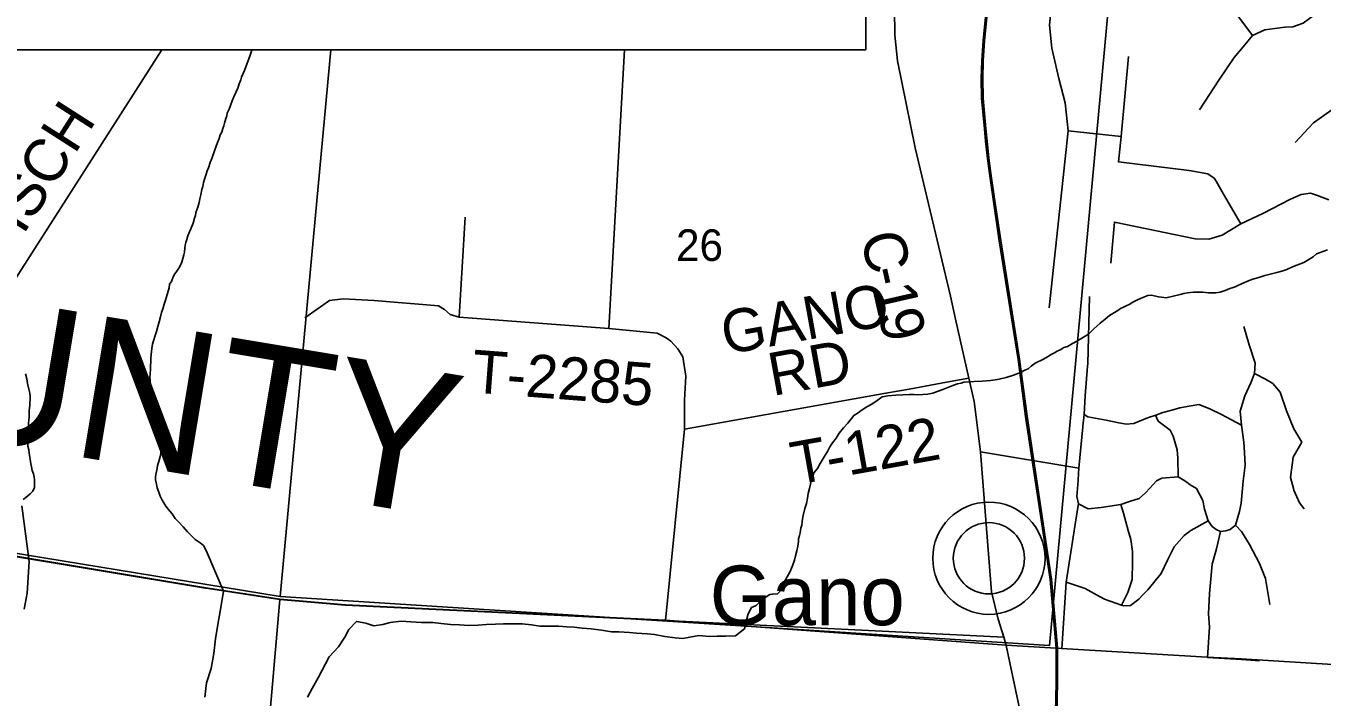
# Model space of a CAD drawing. Extents: x 0 to 34, y 0 to 22.
# Drawn here: x 6.065 to 7.782, y 14.962 to 15.851 of the extents above; entities that cross this region are included whole.
import ezdxf

# ---------------------------------------------------------------- set-up
doc = ezdxf.new("R2010")
doc.units = 0
for name, color, linetype in [('GM_X_County_Road', 7, 'Continuous'), ('GM_X_County_Road_Text', 7, 'Continuous'), ('GM_X_County_Text', 7, 'Continuous'), ('GM_X_Minor_River', 7, 'Continuous'), ('GM_X_Rail_Line', 7, 'Continuous'), ('GM_X_Section', 7, 'Continuous'), ('GM_X_Section_Text', 7, 'Continuous'), ('GM_X_Township_Road', 7, 'Continuous'), ('GM_X_Township_Road_Text', 7, 'Continuous'), ('GM_X_Unincorporated', 7, 'Continuous'), ('GM_X_Unincorporated_Location', 7, 'Continuous'), ('GM_X_Unincorporated_Text', 7, 'Continuous'), ('SH_Cut_Line', 7, 'Continuous'), ('SH_Text', 7, 'Continuous')]:
    doc.layers.add(name, color=color, linetype=linetype)

msp = doc.modelspace()

# ---------------------------------------------------------------- linework, layer by layer
at = {"layer": 'GM_X_County_Road'}
for p, q in [((7.3141, 15.3844), (7.2966, 15.4626)), ((7.3298, 15.2866), (7.3229, 15.34)), ((5.976, 15.1604), (6.3025, 15.106)), ((6.9121, 15.0631), (7.3604, 15.0411))]:
    msp.add_line(p, q, dxfattribs=at)
for points in [[(7.2966, 15.4626), (7.2898, 15.4929), (7.2433, 15.6897), (7.2199, 15.8051), (7.2161, 15.8392), (7.2144, 15.9802), (7.2122, 16.0676), (7.2136, 16.1357), (7.2136, 16.2323), (7.2152, 16.2683), (7.2204, 16.2879), (7.2343, 16.3297), (7.2592, 16.3916), (7.2625, 16.4)], [(7.3229, 15.34), (7.3211, 15.3533), (7.3141, 15.3844)], [(7.3638, 15.0301), (7.3604, 15.0411), (7.3532, 15.0648), (7.3441, 15.1013), (7.3408, 15.1457), (7.3298, 15.2866)], [(6.3025, 15.106), (6.3035, 15.1059), (6.4013, 15.0912)], [(6.3406, 14.4159), (6.3408, 14.4188), (6.3507, 14.5264), (6.3678, 14.7139), (6.3846, 14.9026), (6.4013, 15.0912)], [(6.4013, 15.0912), (6.4883, 15.0834), (6.9121, 15.0631)], [(7.332, 14.1), (7.3371, 14.1566), (7.3386, 14.1728), (7.364, 14.4409), (7.3713, 14.5158), (7.3754, 14.5663), (7.3924, 14.7336), (7.3975, 14.7638), (7.4076, 14.8037), (7.4083, 14.8085), (7.4087, 14.8124), (7.4085, 14.817), (7.4067, 14.8277), (7.3638, 15.0301)]]:
    msp.add_lwpolyline(points, dxfattribs=at)
at = {"layer": 'GM_X_Minor_River'}
for points in [[(6.305, 15.6592), (6.3066, 15.6633), (6.309, 15.6701), (6.311, 15.6754), (6.3146, 15.6856), (6.3166, 15.692), (6.3186, 15.6969), (6.3206, 15.7022), (6.3222, 15.7068), (6.3241, 15.7105), (6.3254, 15.7154), (6.327, 15.7188), (6.3278, 15.7226), (6.3294, 15.7287), (6.331, 15.7321), (6.3315, 15.7355), (6.3342, 15.7411), (6.3358, 15.7456), (6.3382, 15.7521), (6.3402, 15.7573), (6.3454, 15.769), (6.3474, 15.7747), (6.3494, 15.78), (6.3502, 15.7834), (6.3545, 15.792), (6.3574, 15.8007), (6.3601, 15.8075), (6.3617, 15.8124), (6.3637, 15.8177), (6.3645, 15.8198)], [(6.3267, 15.1021), (6.3035, 15.156), (6.2998, 15.1625), (6.2957, 15.166), (6.289, 15.1707), (6.2853, 15.1742), (6.279, 15.1808), (6.2731, 15.1874), (6.2668, 15.194), (6.2624, 15.1983), (6.2583, 15.2045), (6.2532, 15.211), (6.2499, 15.2149), (6.2473, 15.2191), (6.2451, 15.2226), (6.2426, 15.228), (6.2408, 15.2333), (6.2386, 15.2391), (6.2376, 15.2441), (6.2366, 15.2498), (6.2363, 15.2532), (6.2367, 15.2566), (6.2384, 15.2646), (6.2392, 15.2688), (6.2408, 15.274), (6.2425, 15.2805), (6.2433, 15.2846), (6.2434, 15.2896), (6.2439, 15.296), (6.2441, 15.3048), (6.2434, 15.309), (6.2431, 15.3132), (6.24, 15.3243), (6.24, 15.3277), (6.2378, 15.3312), (6.2364, 15.3346), (6.2353, 15.3381), (6.2343, 15.3434), (6.2332, 15.3472), (6.2326, 15.3533), (6.2316, 15.3602), (6.2306, 15.3682), (6.2297, 15.3751), (6.2294, 15.3819), (6.2291, 15.3857), (6.2292, 15.3903), (6.2297, 15.3964), (6.23, 15.4108), (6.2305, 15.4158), (6.2309, 15.4196), (6.2314, 15.4237), (6.2326, 15.4294), (6.2359, 15.4408), (6.2379, 15.4464), (6.2395, 15.4528), (6.2412, 15.4589), (6.2428, 15.4657), (6.2445, 15.4714), (6.2461, 15.4763), (6.2477, 15.4823), (6.2497, 15.488), (6.2509, 15.4922), (6.2546, 15.5043), (6.255, 15.5088), (6.2574, 15.5126), (6.2598, 15.5186), (6.2621, 15.5228), (6.2648, 15.5261), (6.268, 15.5314), (6.2711, 15.5382), (6.274, 15.548), (6.2748, 15.5514), (6.2753, 15.5571), (6.2757, 15.5605), (6.2766, 15.5643), (6.2778, 15.5681), (6.2794, 15.573), (6.2814, 15.5783), (6.283, 15.5824), (6.2862, 15.59), (6.2882, 15.5964), (6.2894, 15.6002), (6.2899, 15.604), (6.2926, 15.6111), (6.2943, 15.6172), (6.2951, 15.6221), (6.2964, 15.6274), (6.2977, 15.6346), (6.2989, 15.6384), (6.3001, 15.6437), (6.3017, 15.6494), (6.3034, 15.6547), (6.305, 15.6592)], [(7.5007, 15.4674), (7.5073, 15.4713), (7.5115, 15.4743), (7.5154, 15.4768), (7.5193, 15.4786), (7.5227, 15.4804), (7.5266, 15.4822), (7.5316, 15.485), (7.537, 15.4879), (7.5428, 15.4904), (7.5513, 15.4939), (7.5558, 15.4946), (7.566, 15.492), (7.5759, 15.4909), (7.5851, 15.4929), (7.5942, 15.4953), (7.5992, 15.4967), (7.6042, 15.4977), (7.6118, 15.4986), (7.6244, 15.4982), (7.6316, 15.4976), (7.6354, 15.4975), (7.6414, 15.4977), (7.6472, 15.4986), (7.6537, 15.5007), (7.6599, 15.5032), (7.6633, 15.5042), (7.6671, 15.5056), (7.6706, 15.5074), (7.6745, 15.5088), (7.6795, 15.5113), (7.6856, 15.5138), (7.6918, 15.5159), (7.6983, 15.518), (7.7063, 15.5204), (7.7224, 15.5245), (7.7289, 15.5262), (7.7355, 15.5286), (7.7432, 15.5322), (7.7582, 15.5378), (7.7706, 15.5454), (7.7748, 15.5491), (7.7894, 15.5543)], [(7.0172, 15.0524), (7.0179, 15.0617), (7.0199, 15.0654), (7.0216, 15.0722), (7.0264, 15.0804), (7.0326, 15.0833), (7.0392, 15.0903), (7.0443, 15.0939), (7.0505, 15.0975), (7.0539, 15.0982), (7.0607, 15.0984), (7.0667, 15.1054), (7.0676, 15.1134), (7.0716, 15.1182), (7.0772, 15.1275), (7.0805, 15.1358), (7.083, 15.1433), (7.0847, 15.1489), (7.0864, 15.1554), (7.0877, 15.1618), (7.0886, 15.1678), (7.0887, 15.1713), (7.0896, 15.1758), (7.0905, 15.1792), (7.0918, 15.1856), (7.0927, 15.1894), (7.0932, 15.1939), (7.0937, 15.1981), (7.0946, 15.2022), (7.0968, 15.2117), (7.0989, 15.2185), (7.1006, 15.2253), (7.1015, 15.2317), (7.1029, 15.2381), (7.1042, 15.2438), (7.1054, 15.2487), (7.1075, 15.2543), (7.1088, 15.2588), (7.1135, 15.2648), (7.1171, 15.2711), (7.1227, 15.2801), (7.1267, 15.2872), (7.1299, 15.2935), (7.1335, 15.2988), (7.1383, 15.3051), (7.1426, 15.3114), (7.1482, 15.3185), (7.1537, 15.3248), (7.1619, 15.3348), (7.1677, 15.3384), (7.1716, 15.3417), (7.179, 15.3464), (7.1848, 15.3497), (7.191, 15.3533), (7.1995, 15.3598), (7.2068, 15.3608), (7.2175, 15.362), (7.2266, 15.3624), (7.2357, 15.3629), (7.2418, 15.3627), (7.2467, 15.3622), (7.2532, 15.3628), (7.2601, 15.3633), (7.2666, 15.3646), (7.2735, 15.3671), (7.2796, 15.3696), (7.2862, 15.372), (7.2931, 15.3749), (7.2992, 15.377), (7.3042, 15.3779), (7.3077, 15.379), (7.3141, 15.3795), (7.3214, 15.3801), (7.332, 15.3805), (7.3431, 15.3813), (7.3492, 15.3823), (7.3545, 15.3832), (7.3637, 15.3852), (7.3733, 15.3884), (7.3829, 15.3919), (7.3883, 15.3948), (7.393, 15.3969), (7.3969, 15.4002), (7.4023, 15.4042), (7.4131, 15.4096), (7.4185, 15.4128), (7.4235, 15.4157), (7.4278, 15.4179), (7.4313, 15.4201), (7.4363, 15.4226), (7.4402, 15.4251), (7.4448, 15.4265), (7.4517, 15.4305), (7.4575, 15.4333), (7.4726, 15.4427), (7.48, 15.4497), (7.4882, 15.4571), (7.4948, 15.4626), (7.5007, 15.4674)], [(6.061, 15.2238), (6.0667, 15.2282), (6.0702, 15.2312), (6.0737, 15.2345), (6.0761, 15.2394), (6.0761, 15.2436), (6.0759, 15.2497), (6.0756, 15.2531), (6.0745, 15.2577), (6.0731, 15.2619), (6.0721, 15.2669), (6.0714, 15.2707), (6.0707, 15.2741), (6.0694, 15.2822), (6.069, 15.2856), (6.0684, 15.2894), (6.0673, 15.2944), (6.0674, 15.2989), (6.0672, 15.3046), (6.0674, 15.3176), (6.0679, 15.3218), (6.068, 15.3252), (6.0684, 15.3286), (6.0689, 15.3331), (6.069, 15.3415), (6.0699, 15.348), (6.07, 15.3518), (6.0701, 15.3556), (6.0705, 15.3597), (6.0699, 15.3647), (6.0685, 15.37), (6.0667, 15.3773), (6.0657, 15.3834), (6.064, 15.3903)], [(6.0691, 15.1414), (6.0593, 15.2154)], [(6.0625, 15.0783), (6.0663, 15.0996), (6.0691, 15.1414)], [(6.3017, 14.9614), (6.304, 14.9804), (6.31, 14.9998), (6.3138, 15.0195), (6.3161, 15.0389), (6.3192, 15.0579), (6.3226, 15.0776), (6.3267, 15.1021)], [(6.438, 14.9617), (6.444, 14.9733), (6.4523, 14.9879), (6.4666, 15.015), (6.479, 15.0284), (6.4873, 15.0411), (6.4924, 15.0513), (6.5029, 15.062), (6.515, 15.0599), (6.5256, 15.0562), (6.5377, 15.0578), (6.5473, 15.0607), (6.5618, 15.0623), (6.5747, 15.0616), (6.5887, 15.0605), (6.6039, 15.0606), (6.6149, 15.0592), (6.6274, 15.0578), (6.6391, 15.0575), (6.6517, 15.0568), (6.6638, 15.0569), (6.6752, 15.0578), (6.687, 15.0583), (6.6977, 15.0588), (6.7102, 15.0589), (6.7223, 15.0587), (6.7345, 15.0573), (6.7455, 15.0559), (6.7576, 15.0556), (6.7705, 15.0557), (6.7815, 15.0547), (6.791, 15.0545), (6.802, 15.0531), (6.8137, 15.0521), (6.8274, 15.0503), (6.8406, 15.0484)], [(6.8406, 15.0484), (6.8505, 15.0482), (6.8645, 15.0472), (6.874, 15.0466), (6.888, 15.0455), (6.8975, 15.0445), (6.9115, 15.0419), (6.9251, 15.0401), (6.935, 15.0395), (6.9445, 15.0412), (6.9563, 15.0432), (6.9704, 15.0421), (6.9806, 15.0423), (6.9917, 15.0424), (7.005, 15.0429), (7.0172, 15.0524)]]:
    msp.add_lwpolyline(points, dxfattribs=at)
at = {"layer": 'GM_X_Rail_Line'}
for points in [[(7.4298, 15.0266), (7.4218, 15.1177), (7.4157, 15.159), (7.3894, 15.3336), (7.3796, 15.4091), (7.3546, 15.5664), (7.3458, 15.6248), (7.3415, 15.6557), (7.3388, 15.6757), (7.3365, 15.6984), (7.3349, 15.7147), (7.3311, 15.7555), (7.3307, 15.7814), (7.3315, 15.8052), (7.333, 15.8316), (7.3366, 15.8672)], [(7.4317, 15.0268), (7.4237, 15.1179), (7.4176, 15.1593), (7.3913, 15.3339), (7.3815, 15.4094), (7.3565, 15.5667), (7.3477, 15.6251), (7.3434, 15.6559), (7.3407, 15.676), (7.3384, 15.6986), (7.3368, 15.7149), (7.333, 15.7556), (7.3326, 15.7814), (7.3334, 15.8052), (7.3349, 15.8314), (7.3385, 15.8669)], [(7.372, 14.1), (7.3761, 14.1592), (7.3883, 14.3378), (7.395, 14.4359), (7.4002, 14.513), (7.4086, 14.6353), (7.426, 14.89), (7.4283, 14.9302), (7.4294, 14.9555), (7.43, 14.986), (7.4298, 15.0266)], [(7.374, 14.1), (7.3781, 14.159), (7.3902, 14.3377), (7.3969, 14.4358), (7.4021, 14.5129), (7.4105, 14.6352), (7.428, 14.8899), (7.4303, 14.9301), (7.4313, 14.9554), (7.4319, 14.986), (7.4317, 15.0268)]]:
    msp.add_lwpolyline(points, dxfattribs=at)
at = {"layer": 'GM_X_Section'}
for points in [[(7.1778, 16.0724), (7.5157, 16.0549), (7.4213, 15.0301), (6.4015, 15.0952), (6.4689, 15.8198)], [(6.4689, 15.8198), (6.4015, 15.0952), (5.3915, 15.2602), (5.4384, 15.8198)]]:
    msp.add_lwpolyline(points, dxfattribs=at)
at = {"layer": 'GM_X_Township_Road'}
for p, q in [((6.0493, 15.5136), (6.2449, 15.8198)), ((6.837, 15.4503), (6.8578, 15.8198)), ((7.446, 15.7123), (7.5163, 15.7047)), ((6.639, 15.4654), (6.6467, 15.5978)), ((7.2351, 15.37), (7.2845, 15.379)), ((7.2845, 15.379), (7.3141, 15.3844)), ((7.6754, 15.322), (7.6737, 15.3406)), ((7.3298, 15.2866), (7.4601, 15.2652))]:
    msp.add_line(p, q, dxfattribs=at)
for points in [[(5.9659, 15.1626), (6.3032, 15.1064), (6.401, 15.0917), (6.488, 15.0839), (6.9119, 15.0636), (7.3636, 15.0306), (7.437, 15.0262), (7.6301, 15.0148), (7.6752, 15.0122), (8.168, 14.9819), (8.3833, 14.9688), (8.525, 14.938), (8.5293, 14.9371), (8.9, 14.8595), (8.9, 19.9667)], [(7.4205, 15.4776), (7.446, 15.7123), (7.442, 15.7492), (7.4336, 15.7815), (7.4242, 15.8219), (7.421, 15.8523), (7.426, 15.9018), (7.4351, 15.9323), (7.4445, 15.9558), (7.4532, 15.991), (7.468, 16.01), (7.4817, 16.0175), (7.4939, 16.0184), (7.509, 16.0182), (7.5282, 16.0121), (7.5444, 15.9926), (7.5555, 15.98), (7.5707, 15.9575), (7.5893, 15.934), (7.6138, 15.9146), (7.6236, 15.9053), (7.629, 15.9012), (7.6629, 15.8752), (7.6902, 15.8387)], [(7.6198, 15.74), (7.6457, 15.7795), (7.6657, 15.8096), (7.68, 15.8261), (7.6902, 15.8387), (7.7063, 15.8461), (7.7329, 15.8496), (7.7435, 15.8499), (7.7571, 15.8548), (7.774, 15.8674), (7.789, 15.8864), (7.8111, 15.9337), (7.8174, 15.9509), (7.8339, 15.9821), (7.8468, 15.9922), (7.8598, 15.9975), (7.9443, 15.9957)], [(7.6747, 15.5891), (7.6519, 15.6282), (7.6421, 15.6454), (7.6393, 15.6497), (7.631, 15.6551), (7.6064, 15.6596), (7.5127, 15.671), (7.5163, 15.7047), (7.5258, 15.8108)], [(7.8252, 15.7559), (7.7954, 15.74), (7.7709, 15.723), (7.7467, 15.6967)], [(7.5023, 15.5369), (7.5072, 15.5912), (7.614, 15.5691), (7.6323, 15.5688), (7.6501, 15.574), (7.6747, 15.5891), (7.7037, 15.6028), (7.7405, 15.6217), (7.7545, 15.628), (7.7669, 15.6294), (7.7761, 15.6266), (7.7911, 15.6207)], [(6.9121, 15.0631), (6.9376, 15.3167), (6.9375, 15.3553), (6.9393, 15.3869), (6.9351, 15.4128), (6.9284, 15.4233), (6.9193, 15.4335), (6.913, 15.438), (6.9014, 15.444), (6.837, 15.4503), (6.639, 15.4654), (6.6268, 15.4689), (6.6194, 15.4755), (6.6113, 15.4801), (6.5263, 15.4874), (6.485, 15.4895), (6.4668, 15.4874), (6.4345, 15.4643)], [(7.4714, 15.4005), (7.4717, 15.4036), (7.4743, 15.4926)], [(7.6737, 15.3406), (7.6799, 15.361), (7.6879, 15.3782), (7.6928, 15.3907), (7.6935, 15.4045), (7.6856, 15.4287), (7.6788, 15.4529)], [(7.4652, 15.3198), (7.4653, 15.3209), (7.4672, 15.3362), (7.4684, 15.3608), (7.4714, 15.4005)], [(7.7443, 15.238), (7.7407, 15.2527), (7.7442, 15.2798), (7.7554, 15.2997), (7.745, 15.3172), (7.7351, 15.341), (7.7267, 15.3659), (7.7172, 15.3772), (7.7075, 15.3833), (7.6928, 15.3907)], [(6.9376, 15.3167), (7.2044, 15.3644), (7.2351, 15.37)], [(7.4672, 15.3362), (7.472, 15.3332), (7.4961, 15.3289), (7.5108, 15.3258), (7.5229, 15.3235), (7.5328, 15.3243), (7.5511, 15.332), (7.562, 15.3353), (7.5714, 15.3391), (7.5832, 15.3418)], [(7.5832, 15.3418), (7.594, 15.3451), (7.6061, 15.3471), (7.6192, 15.3497), (7.6338, 15.3437), (7.649, 15.3362), (7.6754, 15.322)], [(7.6029, 15.2464), (7.5984, 15.2495), (7.5917, 15.2535), (7.591, 15.2783), (7.5902, 15.2896), (7.5848, 15.3077), (7.581, 15.3157), (7.5652, 15.3276), (7.563, 15.3322), (7.562, 15.3353)], [(7.6675, 15.1897), (7.6727, 15.2076), (7.6751, 15.2189), (7.6776, 15.248), (7.6803, 15.2693), (7.6797, 15.2858), (7.6786, 15.2997), (7.6754, 15.322)], [(7.4597, 15.2584), (7.4601, 15.2652), (7.4652, 15.3198)], [(7.4579, 15.2077), (7.4595, 15.2178), (7.4572, 15.2277), (7.4591, 15.2488), (7.4597, 15.2584)], [(7.4595, 15.2178), (7.4723, 15.2114), (7.4896, 15.2132), (7.5158, 15.217), (7.5273, 15.2208), (7.54, 15.2248), (7.5482, 15.2324), (7.5539, 15.2385), (7.5584, 15.2437), (7.5628, 15.2485), (7.57, 15.2517), (7.5917, 15.2535)], [(7.6675, 15.1897), (7.6605, 15.1838), (7.655, 15.1819), (7.6478, 15.1813), (7.6421, 15.184), (7.6368, 15.1878), (7.6314, 15.1955), (7.6264, 15.2106), (7.6241, 15.2221), (7.6157, 15.2381), (7.6075, 15.2432), (7.6029, 15.2464)], [(7.7584, 15.2114), (7.7522, 15.2193), (7.7447, 15.236), (7.7443, 15.238)], [(7.4373, 15.0256), (7.4432, 15.1142), (7.4579, 15.2077)], [(7.5158, 15.217), (7.5192, 15.2053), (7.5254, 15.1825), (7.5289, 15.1708), (7.531, 15.1545), (7.531, 15.1407), (7.5306, 15.1177), (7.525, 15.1004), (7.5167, 15.0837)], [(7.4432, 15.1142), (7.4683, 15.1056), (7.4836, 15.0973), (7.4939, 15.0913), (7.5167, 15.0837), (7.5196, 15.0826), (7.5285, 15.0832), (7.5396, 15.0915), (7.5448, 15.0971), (7.5516, 15.1037), (7.5693, 15.1257), (7.5774, 15.1432), (7.5865, 15.1609), (7.5997, 15.176), (7.6083, 15.1826), (7.6314, 15.1955)], [(7.7132, 15.0843), (7.7074, 15.119), (7.6993, 15.1387), (7.686, 15.164), (7.6754, 15.181), (7.6675, 15.1897)], [(7.6303, 15.0143), (7.6331, 15.0546), (7.632, 15.0721), (7.6333, 15.0991), (7.6366, 15.1378), (7.6422, 15.1584), (7.6478, 15.1813)], [(5.2869, 14.1), (8.9, 14.1), (8.9, 14.8595), (8.5293, 14.9371), (8.525, 14.938), (8.3833, 14.9688), (8.168, 14.9819), (7.6752, 15.0122), (7.6301, 15.0148), (7.437, 15.0262), (7.3636, 15.0306), (6.9119, 15.0636), (6.488, 15.0839), (6.401, 15.0917), (6.3032, 15.1064), (5.9659, 15.1626)], [(7.6303, 15.0143), (7.6754, 15.0117), (7.6995, 15.0097)]]:
    msp.add_lwpolyline(points, dxfattribs=at)
at = {"layer": 'GM_X_Unincorporated'}
for radius in [0.0744, 0.0472]:
    msp.add_circle((7.3408, 15.1457), radius, dxfattribs=at)
at = {"layer": 'GM_X_Unincorporated_Location'}
msp.add_line((7.3408, 15.1457), (7.3408, 15.1457), dxfattribs=at)
at = {"layer": 'SH_Cut_Line'}
for points in [[(5.9659, 15.1626), (6.3032, 15.1064), (6.401, 15.0917), (6.488, 15.0839), (6.9119, 15.0636), (7.3636, 15.0306), (7.437, 15.0262), (7.6301, 15.0148), (7.6752, 15.0122), (8.168, 14.9819), (8.3833, 14.9688), (8.525, 14.938), (8.5293, 14.9371), (8.9, 14.8595), (8.9, 20.9)], [(2.1, 14.1), (8.9, 14.1), (8.9, 14.8595), (8.5293, 14.9371), (8.525, 14.938), (8.3833, 14.9688), (8.168, 14.9819), (7.6752, 15.0122), (7.6301, 15.0148), (7.437, 15.0262), (7.3636, 15.0306), (6.9119, 15.0636), (6.488, 15.0839), (6.401, 15.0917), (6.3032, 15.1064), (5.9659, 15.1626)]]:
    msp.add_lwpolyline(points, dxfattribs=at)
at = {"layer": 'SH_Text'}
msp.add_lwpolyline([(4.8773, 16.4145), (7.1778, 16.4145), (7.1778, 15.8198), (4.8773, 15.8198)], close=True, dxfattribs=at)

# ---------------------------------------------------------------- texts
at = {"layer": 'GM_X_County_Road_Text'}
for s, rotation, p in [('C', 282.8368, (7.1704, 15.5728)), ('-', 282.8479, (7.1807, 15.5273)), ('1', 282.897, (7.1859, 15.5045)), ('9', 283.1703, (7.1938, 15.4701))]:
    msp.add_text(s, height=0.0568, rotation=rotation, dxfattribs=at).set_placement(p)
at = {"layer": 'GM_X_County_Text'}
msp.add_text('BUTLER COUNTY', height=0.189394, rotation=350.5451, dxfattribs=at).set_placement((4.5102, 15.5508))
at = {"layer": 'GM_X_Section_Text'}
msp.add_text('26', height=0.04186, rotation=0, dxfattribs=at).set_placement((6.9262, 15.5398))
at = {"layer": 'GM_X_Township_Road_Text'}
for s, rotation, p in [('WINDISCH', 57.4131, (5.9519, 15.4026)), ('GANO', 10.2411, (6.9917, 15.4155)), ('RD', 10.3487, (7.0542, 15.3607)), ('T-2285', 355.6368, (6.6541, 15.3656)), ('T-122', 10.1546, (7.084, 15.2427))]:
    msp.add_text(s, height=0.05682, rotation=rotation, dxfattribs=at).set_placement(p)
at = {"layer": 'GM_X_Unincorporated_Text'}
msp.add_text('Gano', height=0.07898, rotation=0, dxfattribs=at).set_placement((6.9709, 15.057))

doc.saveas('drawing.dxf')
